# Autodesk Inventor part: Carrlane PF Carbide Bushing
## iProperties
Company: jsm
Title: Carrlane PF Carbide Bushing
Author: Jason McNamara
Shininess: 67.0
PropertySet Name: _Private Model Information
Created: 2001-04
Part Number: Carrlane PF Carbide Bushing
Material: Steel, Mild
Document SubType Name: Modeling
Designer: Jason Mcnamara
Control State: 0
Master: False
Checked Out: False
PropertySet Name: Design Tracking Control
Density: 7.860000000000001
Volumn: 0.09462282334828513
Area: 1.4025406491423043
PropertySet Name: Model Information
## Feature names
1. Extrusion1
2. Fillet1
